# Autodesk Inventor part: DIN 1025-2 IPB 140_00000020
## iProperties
Created: 2006-02
Part Number: DIN 1025-2 IPB 140_00000020
Material: Default
Document SubType Name: Modeling
Designer: 40664
Manufacturer: Standard
Standards Organization: Custom
Stock Number: DIN 1025-2 IPB 140
Mass: 10266.5 g
Surface Area: 19334.9 cm^2
Volume: 10266.5 cm^3
Density: 1 g/cm^3
G_L: 2390.000 mm
G_W: 140.000 mm
G_H: 140.000 mm
AFG_Item: IPB 140
CSToolsMass: 10.0
CSToolsVolume: 10266466.0
CSToolsArea: 19335.0
Author: 40664
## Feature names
1. AFG_Detailed_DIN 1025-2 IPB 140_00000020 [Extrusion]
2. AFG_Simplified_DIN 1025-2 IPB 140_00000020 [Extrusion]
